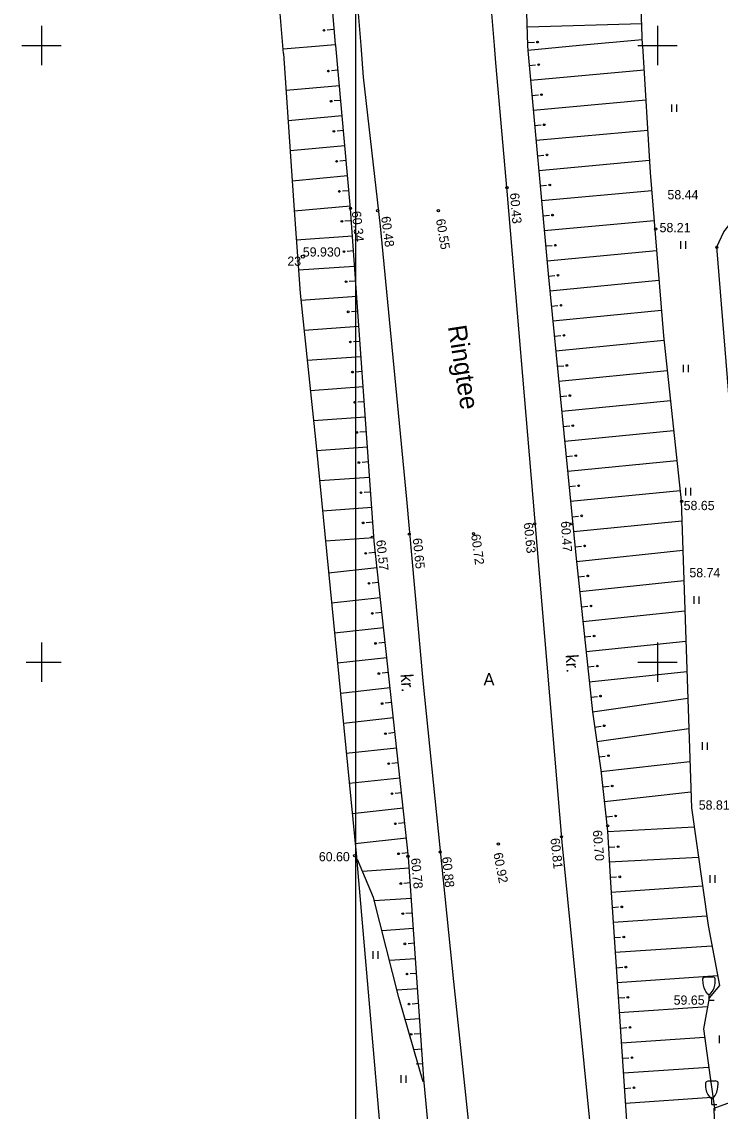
# Model space of a CAD drawing. Extents: x 9156 to 9809, y 2728 to 4000.
# Drawn here: x 9248.4 to 9305.1, y 3413.6 to 3501.9 of the extents above; entities that cross this region are included whole.
import ezdxf

# ---------------------------------------------------------------- set-up
doc = ezdxf.new("R2010")
doc.units = 0
for name, color, linetype in [('Level 54', 7, 'Continuous'), ('Level 58', 7, 'Continuous'), ('Level 63', 7, 'Continuous')]:
    doc.layers.add(name, color=color, linetype=linetype)

# ---------------------------------------------------------------- blocks, each defined once
blk = doc.blocks.new('KKOL')
at = {"layer": 'Level 58'}
for p, q in [((0, 1.59349), (0, -1.5935)), ((-1.5935, 0), (1.59349, 0))]:
    blk.add_line(p, q, dxfattribs=at)

msp = doc.modelspace()

# ---------------------------------------------------------------- linework, layer by layer
at = {"layer": 'Level 54'}
for p, q in [((9272.688, 3540.803), (9275.918, 3500)), ((9286.774, 3500), (9284.599, 3526.285)), ((9269.604, 3500), (9267.616, 3523.296)), ((9250, 3501.593), (9250, 3500)), ((9250, 3501.593), (9250, 3500)), ((9250, 3501.593), (9250, 3500)), ((9250, 3501.593), (9250, 3500)), ((9250, 3501.593), (9250, 3500)), ((9250, 3501.593), (9250, 3500)), ((9298.725, 3501.773), (9289.449, 3501.487)), ((9300, 3501.593), (9300, 3500)), ((9300, 3501.593), (9300, 3500)), ((9250, 3501.25), (9250, 3498.75)), ((9273.708, 3501.296), (9273.184, 3501.253)), ((9300, 3501.25), (9300, 3498.75)), ((9248.407, 3500), (9250, 3500)), ((9248.407, 3500), (9250, 3500)), ((9248.407, 3500), (9250, 3500)), ((9248.75, 3500), (9251.25, 3500)), ((9250, 3500), (9250, 3498.407)), ((9250, 3500), (9251.593, 3500)), ((9250, 3500), (9250, 3498.407)), ((9250, 3500), (9251.593, 3500)), ((9250, 3500), (9250, 3498.407)), ((9250, 3500), (9251.593, 3500)), ((9250, 3500), (9251.593, 3500)), ((9250, 3500), (9251.593, 3500)), ((9250, 3500), (9251.593, 3500)), ((9269.659, 3499.356), (9269.604, 3500)), ((9269.627, 3499.728), (9272.906, 3500)), ((9272.906, 3500), (9273.81, 3500.075)), ((9275.918, 3500), (9276.12, 3497.444)), ((9286.89, 3498.593), (9286.774, 3500)), ((9293.676, 3500), (9289.47, 3499.614)), ((9289.487, 3500.262), (9290.012, 3500.278)), ((9298.76, 3500.466), (9293.676, 3500)), ((9298.407, 3500), (9301.593, 3500)), ((9298.407, 3500), (9301.593, 3500)), ((9298.407, 3500), (9301.593, 3500)), ((9298.407, 3500), (9301.593, 3500)), ((9298.75, 3500), (9301.25, 3500)), ((9300, 3500), (9300, 3498.407)), ((9300, 3500), (9300, 3498.407)), ((9274.067, 3497.996), (9273.543, 3497.948)), ((9287.791, 3488.198), (9286.89, 3498.593)), ((9289.582, 3498.394), (9290.105, 3498.442)), ((9298.91, 3498.018), (9289.694, 3497.173)), ((9276.12, 3497.444), (9277.489, 3485.347)), ((9269.856, 3496.38), (9274.179, 3496.775)), ((9274.29, 3495.555), (9273.767, 3495.507)), ((9289.806, 3495.953), (9290.329, 3496.001)), ((9299.059, 3495.571), (9289.918, 3494.733)), ((9301.131, 3495.235), (9301.131, 3494.615)), ((9301.536, 3495.224), (9301.536, 3494.615)), ((9270.018, 3493.933), (9274.402, 3494.334)), ((9290.029, 3493.512), (9290.553, 3493.56)), ((9274.513, 3493.114), (9273.99, 3493.066)), ((9299.208, 3493.123), (9290.141, 3492.292)), ((9270.18, 3491.487), (9274.625, 3491.893)), ((9290.253, 3491.071), (9290.777, 3491.119)), ((9274.737, 3490.673), (9274.213, 3490.625)), ((9299.357, 3490.675), (9290.365, 3489.851)), ((9270.342, 3489.04), (9274.848, 3489.452)), ((9290.477, 3488.63), (9291.001, 3488.678)), ((9274.96, 3488.232), (9274.436, 3488.184)), ((9290.033, 3461.689), (9287.791, 3488.198)), ((9299.535, 3488.23), (9290.589, 3487.41)), ((9270.504, 3486.594), (9275.071, 3487.011)), ((9275.163, 3485.789), (9274.638, 3485.752)), ((9290.701, 3486.189), (9291.224, 3486.237)), ((9299.731, 3485.787), (9290.813, 3484.969)), ((9277.489, 3485.347), (9279.618, 3463.219)), ((9270.68, 3484.244), (9275.249, 3484.567)), ((9301.878, 3484.144), (9301.878, 3483.524)), ((9302.284, 3484.133), (9302.284, 3483.524)), ((9275.335, 3483.344), (9274.811, 3483.307)), ((9290.925, 3483.748), (9291.448, 3483.796)), ((9299.927, 3483.343), (9291.037, 3482.528)), ((9270.864, 3481.8), (9275.422, 3482.122)), ((9291.15, 3481.308), (9291.673, 3481.359)), ((9275.508, 3480.899), (9274.984, 3480.862)), ((9300.118, 3480.958), (9291.27, 3480.088)), ((9271.063, 3479.357), (9275.594, 3479.677)), ((9291.39, 3478.868), (9291.913, 3478.92)), ((9275.681, 3478.454), (9275.156, 3478.417)), ((9300.314, 3478.514), (9291.51, 3477.649)), ((9271.317, 3476.917), (9275.767, 3477.232)), ((9275.854, 3476.009), (9275.329, 3475.972)), ((9291.629, 3476.429), (9292.153, 3476.48)), ((9300.521, 3476.072), (9291.749, 3475.209)), ((9271.572, 3474.478), (9275.94, 3474.787)), ((9302.082, 3474.122), (9302.082, 3473.502)), ((9302.487, 3474.11), (9302.487, 3473.502)), ((9276.026, 3473.564), (9275.502, 3473.527)), ((9291.869, 3473.99), (9292.393, 3474.041)), ((9300.783, 3473.635), (9291.989, 3472.77)), ((9271.826, 3472.039), (9276.113, 3472.342)), ((9292.109, 3471.55), (9292.633, 3471.602)), ((9276.199, 3471.119), (9275.675, 3471.082)), ((9301.046, 3471.198), (9292.229, 3470.33)), ((9272.08, 3469.599), (9276.285, 3469.897)), ((9292.349, 3469.111), (9292.872, 3469.162)), ((9276.372, 3468.674), (9275.847, 3468.637)), ((9301.308, 3468.76), (9292.469, 3467.891)), ((9272.332, 3467.16), (9276.458, 3467.452)), ((9276.544, 3466.229), (9276.02, 3466.192)), ((9292.589, 3466.671), (9293.112, 3466.723)), ((9301.57, 3466.323), (9292.709, 3465.452)), ((9272.572, 3464.72), (9276.631, 3465.006)), ((9276.717, 3463.784), (9276.193, 3463.747)), ((9292.829, 3464.232), (9293.352, 3464.284)), ((9301.833, 3463.886), (9292.949, 3463.012)), ((9302.272, 3464.137), (9302.272, 3463.517)), ((9302.678, 3464.126), (9302.678, 3463.517)), ((9279.618, 3463.219), (9280.964, 3448.483)), ((9272.812, 3462.279), (9276.804, 3462.561)), ((9293.069, 3461.793), (9293.592, 3461.844)), ((9276.89, 3461.339), (9276.365, 3461.302)), ((9292.271, 3435.404), (9290.033, 3461.689)), ((9301.974, 3461.437), (9293.189, 3460.573)), ((9273.052, 3459.839), (9276.976, 3460.116)), ((9293.309, 3459.353), (9293.832, 3459.405)), ((9277.098, 3458.897), (9276.575, 3458.84)), ((9302.053, 3459.047), (9293.433, 3458.134)), ((9273.307, 3457.25), (9277.231, 3457.679)), ((9277.364, 3456.46), (9276.841, 3456.403)), ((9293.562, 3456.915), (9294.085, 3456.971)), ((9302.135, 3456.591), (9293.691, 3455.697)), ((9273.547, 3454.81), (9277.497, 3455.242)), ((9302.952, 3455.342), (9302.952, 3454.722)), ((9303.357, 3455.331), (9303.357, 3454.722)), ((9277.631, 3454.024), (9277.108, 3453.967)), ((9293.82, 3454.478), (9294.343, 3454.533)), ((9302.217, 3454.134), (9293.949, 3453.259)), ((9273.787, 3452.371), (9277.764, 3452.805)), ((9294.078, 3452.04), (9294.601, 3452.096)), ((9250, 3451.593), (9250, 3448.407)), ((9250, 3451.25), (9250, 3448.75)), ((9277.897, 3451.587), (9277.374, 3451.53)), ((9302.299, 3451.678), (9294.207, 3450.822)), ((9300, 3451.25), (9300, 3448.75)), ((9274.027, 3449.931), (9278.03, 3450.369)), ((9248.75, 3450), (9251.25, 3450)), ((9250, 3450), (9251.593, 3450)), ((9294.336, 3449.603), (9294.859, 3449.658)), ((9298.75, 3450), (9301.25, 3450)), ((9278.163, 3449.151), (9277.641, 3449.093)), ((9280.964, 3448.483), (9283.432, 3424.105)), ((9302.38, 3449.222), (9294.465, 3448.384)), ((9274.266, 3447.492), (9278.297, 3447.932)), ((9278.43, 3446.714), (9277.907, 3446.657)), ((9294.594, 3447.165), (9295.117, 3447.221)), ((9302.452, 3447.047), (9294.724, 3445.947)), ((9274.506, 3445.052), (9278.563, 3445.496)), ((9278.696, 3444.277), (9278.173, 3444.22)), ((9294.897, 3444.733), (9295.418, 3444.807)), ((9302.534, 3444.583), (9295.07, 3443.52)), ((9303.631, 3443.5), (9303.631, 3442.88)), ((9304.037, 3443.489), (9304.037, 3442.88)), ((9274.746, 3442.613), (9278.829, 3443.059)), ((9295.243, 3442.307), (9295.763, 3442.381)), ((9278.963, 3441.841), (9278.44, 3441.784)), ((9302.623, 3441.91), (9295.411, 3441.093)), ((9274.986, 3440.173), (9279.096, 3440.622)), ((9295.549, 3439.875), (9296.071, 3439.934)), ((9279.229, 3439.404), (9278.706, 3439.347)), ((9302.705, 3439.452), (9295.687, 3438.657)), ((9275.226, 3437.734), (9279.362, 3438.186)), ((9295.825, 3437.439), (9296.347, 3437.499)), ((9279.495, 3436.967), (9278.973, 3436.91)), ((9302.973, 3436.599), (9295.959, 3436.221)), ((9275.466, 3435.294), (9279.629, 3435.749)), ((9294.513, 3412.817), (9292.271, 3435.404)), ((9279.762, 3434.531), (9279.239, 3434.474)), ((9296.025, 3434.997), (9296.55, 3435.026)), ((9276.942, 3430.907), (9275.652, 3434.001)), ((9303.32, 3434.163), (9296.09, 3433.774)), ((9276.05, 3433.048), (9279.859, 3433.309)), ((9296.156, 3432.55), (9296.681, 3432.578)), ((9304.243, 3432.728), (9304.243, 3432.108)), ((9304.649, 3432.717), (9304.649, 3432.108)), ((9279.943, 3432.087), (9279.419, 3432.051)), ((9303.652, 3431.832), (9296.234, 3431.327)), ((9279.017, 3422.808), (9276.942, 3430.907)), ((9277.006, 3430.657), (9280.027, 3430.864)), ((9296.317, 3430.104), (9296.842, 3430.14)), ((9280.111, 3429.641), (9279.586, 3429.605)), ((9303.999, 3429.399), (9296.4, 3428.881)), ((9277.625, 3428.242), (9280.195, 3428.419)), ((9296.484, 3427.659), (9297.008, 3427.694)), ((9276.898, 3426.566), (9276.898, 3425.945)), ((9277.304, 3426.554), (9277.304, 3425.945)), ((9280.278, 3427.196), (9279.754, 3427.16)), ((9304.419, 3426.97), (9296.567, 3426.436)), ((9278.244, 3425.828), (9280.362, 3425.973)), ((9280.446, 3424.75), (9279.922, 3424.714)), ((9296.65, 3425.213), (9297.175, 3425.249)), ((9283.432, 3424.105), (9285.001, 3409.415)), ((9304.872, 3424.545), (9296.733, 3423.99)), ((9303.886, 3424.474), (9304.486, 3424.474)), ((9278.845, 3423.412), (9280.53, 3423.528)), ((9304.086, 3423.074), (9304.286, 3423.074)), ((9304.186, 3422.574), (9304.186, 3423.074)), ((9280.98, 3415.947), (9279.017, 3422.808)), ((9280.614, 3422.305), (9280.089, 3422.269)), ((9296.817, 3422.768), (9297.341, 3422.803)), ((9304.051, 3422.032), (9296.9, 3421.545)), ((9304.186, 3422.574), (9304.586, 3422.574)), ((9279.534, 3421.003), (9280.698, 3421.082)), ((9296.983, 3420.322), (9297.508, 3420.358)), ((9280.781, 3419.86), (9280.257, 3419.824)), ((9303.824, 3419.56), (9297.066, 3419.099)), ((9304.991, 3419.727), (9304.991, 3419.107)), ((9280.223, 3418.593), (9280.865, 3418.637)), ((9297.15, 3417.877), (9297.674, 3417.912)), ((9280.949, 3417.414), (9280.424, 3417.378)), ((9304.151, 3417.125), (9297.233, 3416.654)), ((9279.162, 3416.495), (9279.162, 3415.875)), ((9279.568, 3416.484), (9279.568, 3415.875)), ((9281.483, 3411.478), (9281.033, 3416.192)), ((9304.114, 3416.033), (9304.714, 3416.033)), ((9297.316, 3415.431), (9297.841, 3415.467)), ((9304.414, 3414.686), (9297.399, 3414.208)), ((9304.314, 3414.633), (9304.514, 3414.633)), ((9304.414, 3414.133), (9304.414, 3414.633)), ((9304.414, 3414.133), (9304.814, 3414.133))]:
    msp.add_line(p, q, dxfattribs=at)
for points in [[(9250, 3738.614), (9253.398, 3731.987), (9257.522, 3722.336), (9261.761, 3711.307), (9265.539, 3700.09), (9268.174, 3688.256), (9270.465, 3677.226), (9272.41, 3666.239), (9275.847, 3643.259), (9278.136, 3622.295), (9281, 3595.752), (9283.628, 3570.325), (9285.461, 3545.046), (9287.293, 3525.67), (9289.24, 3507.056), (9289.458, 3500)], [(9298.789, 3500), (9298.217, 3515.72), (9298.103, 3526.407), (9296.155, 3540.196), (9294.785, 3549.211), (9292.952, 3569.435), (9290.202, 3589.084), (9286.767, 3619.468), (9285.736, 3621.307), (9285.048, 3622.915), (9284.705, 3624.754), (9285.736, 3627.512), (9286.423, 3629.465), (9282.989, 3666.871), (9279.667, 3687.502), (9279.324, 3696.006), (9278.522, 3701.406), (9275.886, 3702.9), (9273.137, 3704.049)], [(9273.876, 3500.081), (9272.272, 3519.386), (9269.408, 3548.573), (9267.81, 3566.423), (9265.862, 3587.452), (9263.341, 3611.469), (9261.628, 3624.411), (9261.147, 3625.256), (9258.368, 3625.604), (9250.237, 3627.671)], [(9273.884, 3500), (9273.876, 3500.081)], [(9281.033, 3416.192), (9279.799, 3434.189), (9276.998, 3459.808), (9275.093, 3486.775), (9273.884, 3500)], [(9289.458, 3500), (9289.47, 3499.614)], [(9298.79, 3499.978), (9298.789, 3500)], [(9298.79, 3499.978), (9299.417, 3489.696), (9300.479, 3476.464), (9301.919, 3463.08), (9302.747, 3438.183), (9304.109, 3428.626), (9305.019, 3423.759), (9304.185, 3422.77), (9303.73, 3420.261), (9304.261, 3416.306), (9304.64, 3413.644)], [(9269.659, 3499.356), (9270.5, 3486.645), (9271.005, 3479.917), (9272.295, 3467.544), (9275.546, 3434.48), (9278.013, 3406.052), (9283.336, 3347.029)], [(9289.47, 3499.614), (9291.132, 3481.488), (9293.375, 3458.682), (9294.721, 3445.971), (9295.394, 3441.246), (9295.954, 3436.297), (9296.179, 3432.135), (9297.523, 3412.394), (9298.42, 3399.908), (9299.093, 3392.259), (9303.013, 3351.953)], [(9304.588, 3413.83), (9306.439, 3414.497), (9308.514, 3414.779), (9309.804, 3415.172), (9310.644, 3415.967), (9310.925, 3416.522), (9310.701, 3417.872), (9310.308, 3421.303), (9308.515, 3437.816), (9305.882, 3470.731), (9304.816, 3483.667), (9305.377, 3484.886), (9308.293, 3488.598), (9308.237, 3489.273), (9308.293, 3490.06), (9307.156, 3497.571)], [(9304.086, 3423.074), (9303.928, 3423.287), (9303.863, 3423.399), (9303.786, 3423.574), (9303.725, 3423.8), (9303.701, 3423.956), (9303.686, 3424.274), (9303.688, 3424.316), (9303.718, 3424.387), (9303.758, 3424.424), (9303.886, 3424.474)], [(9304.286, 3423.074), (9304.444, 3423.287), (9304.509, 3423.399), (9304.586, 3423.574), (9304.647, 3423.8), (9304.671, 3423.956), (9304.686, 3424.274), (9304.684, 3424.316), (9304.654, 3424.387), (9304.614, 3424.424), (9304.486, 3424.474)], [(9304.314, 3414.633), (9304.155, 3414.846), (9304.091, 3414.958), (9304.014, 3415.133), (9303.952, 3415.358), (9303.929, 3415.514), (9303.914, 3415.833), (9303.916, 3415.875), (9303.945, 3415.946), (9303.985, 3415.983), (9304.114, 3416.033)], [(9304.514, 3414.633), (9304.672, 3414.846), (9304.736, 3414.958), (9304.814, 3415.133), (9304.875, 3415.358), (9304.898, 3415.514), (9304.914, 3415.833), (9304.911, 3415.875), (9304.882, 3415.946), (9304.842, 3415.983), (9304.714, 3416.033)], [(9309.451, 3351.529), (9307.769, 3370.966), (9305.414, 3393.823), (9304.853, 3406.365), (9304.588, 3413.83), (9306.439, 3414.497), (9307.208, 3414.445), (9308.666, 3393.762), (9310.796, 3370.615), (9312.132, 3352.15)]]:
    msp.add_lwpolyline(points, dxfattribs=at)
for centre, radius in [((9272.929, 3501.239), 0.0683), ((9290.268, 3500.279), 0.0683), ((9273.288, 3497.932), 0.0683), ((9290.36, 3498.458), 0.0683), ((9273.511, 3495.491), 0.0683), ((9290.584, 3496.017), 0.0683), ((9290.808, 3493.576), 0.0683), ((9273.735, 3493.05), 0.0683), ((9291.032, 3491.135), 0.0683), ((9273.958, 3490.609), 0.0683), ((9287.781, 3488.48), 0.0909), ((9291.256, 3488.694), 0.0683), ((9274.181, 3488.168), 0.0683), ((9275.082, 3486.801), 0.0909), ((9277.297, 3486.604), 0.0909), ((9282.219, 3486.604), 0.0909), ((9274.383, 3485.742), 0.0683), ((9291.48, 3486.253), 0.0683), ((9299.841, 3485.123), 0.0909), ((9291.703, 3483.812), 0.0683), ((9271.218, 3482.888), 0.125), ((9274.555, 3483.297), 0.0683), ((9304.812, 3483.642), 0.0909), ((9291.928, 3481.377), 0.0683), ((9274.728, 3480.852), 0.0683), ((9292.168, 3478.937), 0.0683), ((9274.901, 3478.407), 0.0683), ((9275.074, 3475.962), 0.0683), ((9292.408, 3476.498), 0.0683), ((9292.648, 3474.059), 0.0683), ((9275.246, 3473.517), 0.0683), ((9292.888, 3471.619), 0.0683), ((9275.419, 3471.071), 0.0683), ((9293.127, 3469.18), 0.0683), ((9275.592, 3468.626), 0.0683), ((9275.765, 3466.181), 0.0683), ((9293.367, 3466.74), 0.0683), ((9275.937, 3463.736), 0.0683), ((9293.607, 3464.301), 0.0683), ((9301.954, 3463.042), 0.0909), ((9293.847, 3461.862), 0.0683), ((9276.11, 3461.291), 0.0683), ((9290.038, 3461.215), 0.0909), ((9293.041, 3461.215), 0.0909), ((9276.847, 3460.129), 0.0909), ((9279.849, 3460.376), 0.0909), ((9285.067, 3460.425), 0.0909), ((9294.087, 3459.422), 0.0683), ((9276.32, 3458.82), 0.0683), ((9276.587, 3456.383), 0.0683), ((9294.34, 3456.99), 0.0683), ((9276.853, 3453.946), 0.0683), ((9294.598, 3454.553), 0.0683), ((9294.856, 3452.115), 0.0683), ((9277.119, 3451.51), 0.0683), ((9295.114, 3449.678), 0.0683), ((9277.386, 3449.073), 0.0683), ((9295.372, 3447.24), 0.0683), ((9277.652, 3446.636), 0.0683), ((9277.919, 3444.2), 0.0683), ((9295.672, 3444.836), 0.0683), ((9296.017, 3442.409), 0.0683), ((9278.185, 3441.763), 0.0683), ((9296.326, 3439.955), 0.0683), ((9278.451, 3439.327), 0.0683), ((9296.602, 3437.52), 0.0683), ((9278.718, 3436.89), 0.0683), ((9295.947, 3436.721), 0.0909), ((9287.087, 3435.24), 0.0909), ((9292.206, 3435.832), 0.0909), ((9275.422, 3434.302), 0.0909), ((9278.984, 3434.453), 0.0683), ((9279.753, 3434.253), 0.0909), ((9282.362, 3434.598), 0.0909), ((9296.805, 3435.032), 0.0683), ((9296.937, 3432.584), 0.0683), ((9279.163, 3432.041), 0.0683), ((9297.097, 3430.15), 0.0683), ((9279.331, 3429.595), 0.0683), ((9297.264, 3427.704), 0.0683), ((9279.498, 3427.15), 0.0683), ((9279.666, 3424.704), 0.0683), ((9297.43, 3425.259), 0.0683), ((9297.597, 3422.813), 0.0683), ((9279.834, 3422.259), 0.0683), ((9297.763, 3420.368), 0.0683), ((9280.001, 3419.814), 0.0683), ((9297.93, 3417.922), 0.0683), ((9298.096, 3415.477), 0.0683)]:
    msp.add_circle(centre, radius, dxfattribs=at)
at = {"layer": 'Level 63'}
msp.add_lwpolyline([(9275.527, 3966.797), (9801.617, 3966.797), (9801.617, 3329.636), (9275.527, 3329.636)], close=True, dxfattribs=at)

# ---------------------------------------------------------------- block references
at = {"layer": 'Level 54'}
msp.add_blockref('KKOL', (9300, 3450), dxfattribs=at)

# ---------------------------------------------------------------- texts
for s, height, p in [('58.44', 0.75, (9300.809, 3487.531)), ('58.21', 0.75, (9300.169, 3484.865)), ('59.930', 0.75, (9271.218, 3482.888)), ('23', 0.75, (9269.96, 3482.138)), ('58.65', 0.75, (9302.122, 3462.326)), ('58.74', 0.75, (9302.589, 3456.879)), ('A', 1, (9285.878, 3448.103)), ('58.81', 0.75, (9303.346, 3438.032)), ('60.60', 0.75, (9272.516, 3433.844)), ('59.65', 0.75, (9301.31, 3422.211))]:
    msp.add_text(s, height=height, dxfattribs=at).set_placement(p)
for s, height, rotation, p in [('60.43', 0.75, 274.80686, (9288.023, 3488.026)), ('60.34', 0.75, 276.25313, (9275.181, 3486.545)), ('60.48', 0.75, 277.61844, (9277.569, 3486.11)), ('60.55', 0.75, 279.43534, (9282.018, 3485.887)), ('Ringtee', 1.5, 278.81799, (9282.984, 3477.222)), ('60.63', 0.75, 276.02036, (9289.129, 3461.284)), ('60.47', 0.75, 273.80294, (9292.157, 3461.406)), ('60.65', 0.75, 275.7276, (9280.132, 3460.029)), ('60.72', 0.75, 277.68984, (9284.87, 3460.333)), ('60.57', 0.75, 276.09791, (9277.168, 3459.875)), ('kr.', 1, 273.68076, (9292.535, 3450.59)), ('kr.', 1, 273.68076, (9279.146, 3449.01)), ('60.70', 0.75, 274.56078, (9294.741, 3436.346)), ('60.81', 0.75, 275.92983, (9291.313, 3435.692)), ('60.92', 0.75, 280.94124, (9286.674, 3434.478)), ('60.78', 0.75, 275.34042, (9279.988, 3434.08)), ('60.88', 0.75, 276.19782, (9282.507, 3434.177))]:
    msp.add_text(s, height=height, rotation=rotation, dxfattribs=at).set_placement(p)

doc.saveas('drawing.dxf')
